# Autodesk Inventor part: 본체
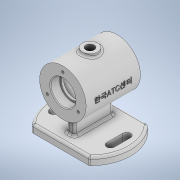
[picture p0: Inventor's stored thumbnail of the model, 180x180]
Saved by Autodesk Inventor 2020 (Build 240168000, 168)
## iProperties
Created: 2021-09
Part Number: 본체
Material: 일반
Document SubType Name: Modeling
Designer: Administrator
Density: 1 g/cm^3
Appearance: 기본값
Author: Administrator
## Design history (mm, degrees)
sketch "스케치1"
  geometry: C1 r 30 at (0, 62); 1 further point
  constraints: 1 centre point, 1 vertical alignment
  dimensions: "d0" = 60 diameter of C1; "d1" = 62 distance of point (0, 0) C1.centre
extrude "돌출1" new body sketch "스케치1" stored distance "d2" = 70; taper "d3" = 0 deg
node "작업 평면1"
sketch "스케치2"
  geometry: L1 (30, 35)-(-30, 35) reference; L2 (30, -35)-(30, 35) reference; C1 r 10 at (0, 0); 1 further point
  constraints: 1 centre point, 1 coincident
  dimensions: "d5" = 35 distance from line of L1 C1.centre; "d65" = 20 diameter of C1
extrude "돌출2" join sketch "스케치2" distance "d6" = 33; taper "d7" = 0 deg
sketch "스케치8"
  geometry: L1 (44.119, 25)-(0, 25); L2 (0, 25)-(0, -25); L3 (0, -25)-(44.119, -25); L4 (44.119, -25)-(44.119, 25); 2 further points
  constraints: 8 end point, 2 parallel, 1 coincident, 1 horizontal, 1 midpoint, 1 perpendicular
  dimensions: "d38" = 50 distance between parallel lines of L3 L1
extrude "돌출6" join sketch "스케치8" stored distance "d39" = 10; taper "d40" = 0 deg
sketch "스케치3"
  geometry: L1 (92, 35)-(32, 35) reference; L2 (32, -35)-(92, -35) reference; L3 (62, 35)-(62, -35); L4 (62, 35)-(78, 35); L5 (78, 35)-(78, 23); L6 (78, 23)-(76, 23); L7 (76, 23)-(76, 20); L8 (76, 20)-(87, 20); L9 (87, 20)-(87, -20); L10 (87, -20)-(76, -20); L11 (76, -20)-(76, -23); L12 (76, -23)-(78, -23); L13 (78, -23)-(78, -35); 1 further point
  constraints: 22 end point, 8 perpendicular, 2 midpoint, 2 point on line, 1 vertical
  dimensions: "d8" = 32 diameter of L5 L3; "d9" = 28 diameter of L7 L3; "d10" = 50 diameter of L9 L3; "d11" = 28 diameter of L11 L3; "d12" = 32 diameter of L13 L3; "d13" = 12 distance from line of L5.end L4; "d14" = 3 distance from line of L8 L5.end; "d15" = 12 distance from line of L2 L11.end; "d16" = 3 distance from line of L11.end L10
revolve "회전1" sketch "스케치3" stored, may be unused: angle "d17" = 90 deg
sketch "스케치4"
  geometry: C1 r 10 at (0, 0) reference; 2 further points
  constraints: 1 coincident
hole "구멍1" sketch "스케치4" at (0, 0) diameter "d18" = 10.917; stored, may be unused: countersink angle "d22" = 90 deg, drill point angle "d24" = 0 deg; dims "d19" = 24, "d20" = 4, "d21" = 2, "d23" = 29.1
sketch "스케치5"
  geometry: C1 r 52.5 at (0, 0); 1 further point
  constraints: 1 centre point, 1 coincident
  dimensions: "d25" = 105 diameter of C1
extrude "돌출3" join sketch "스케치5" distance "d26" = 10; taper "d27" = 0 deg
sketch "스케치6"
  geometry: L1 (-63.077, -37.5)-(63.077, -37.5); L2 (63.077, -37.5)-(63.077, -66.25); L3 (63.077, -66.25)-(-63.077, -66.25); L4 (-63.077, -66.25)-(-63.077, -37.5); L5 (-63.077, 66.25)-(63.077, 66.25); L6 (63.077, 66.25)-(63.077, 37.5); L7 (63.077, 37.5)-(-63.077, 37.5); L8 (-63.077, 37.5)-(-63.077, 66.25); 3 further points
  constraints: 16 end point, 4 parallel, 2 equal length, 2 horizontal, 2 midpoint, 2 perpendicular, 2 vertical alignment
  dimensions: "d28" = 75 distance between parallel lines of L1 L7; "d29" = 37.5 distance from line of point (0, 0) L1
extrude "돌출4" cut sketch "스케치6" extent not by distance; stored distance "d30" = 0; taper "d31" = 0 deg
sketch "스케치7"
  geometry: L1 (-37, 10)-(-37, -10); L2 (-42, 10)-(-42, -10); L3 (-32, -10)-(-32, 10); L4 (37, 10.422)-(37, -10.422); L5 (32, 10.422)-(32, -10.422); L6 (42, -10.422)-(42, 10.422); A1 r 5 centre (-37, 10) between (-32, 10) and (-42, 10); A2 r 5 centre (-37, -10) between (-42, -10) and (-32, -10); A3 r 5 centre (37, 10.422) between (42, 10.422) and (32, 10.422); A4 r 5 centre (37, -10.422) between (32, -10.422) and (42, -10.422); 3 further points
  constraints: 16 end point, 8 point on circle, 8 tangent, 4 centre point, 3 parallel, 2 horizontal alignment, 2 midpoint, 1 equal radius, 1 vertical
  dimensions: "d32" = 20 distance of L1.end L1.start; "d33" = 37 distance of point (0, 0) point (-37, 0); "d34" = 37 distance of point (37, 0) point (0, 0); "d35" = 10 distance between parallel lines of L2 L3
extrude "돌출5" cut sketch "스케치7" extent not by distance; stored distance "d36" = 0; taper "d37" = 0 deg
sketch "스케치9"
  geometry: C1 r 16 at (0, 0) reference; 4 further points
  constraints: 4 other
  dimensions: "d41" = 23 distance of C1.centre point (0, 23); "d44" = 360 deg dimension on C1.centre point (0, 23) (derived)
hole "구멍2" sketch "스케치9" at (0, 23), (-19.919, -11.5), (19.919, -11.5) diameter "d46" = 3.242; stored, may be unused: countersink angle "d50" = 90 deg, drill point angle "d52" = 118 deg; dims "d47" = 8, "d48" = 4, "d49" = 2, "d51" = 10
fillet "모깎기1" dims "d53" = 3
fillet "모깎기2" dims "d54" = 0.3
chamfer "모따기1" distance "d55" = 1; stored, may be unused: second distance "d56" = 2, angle "d57" = 45 deg
fillet "모깎기3" dims "d58" = 3
fillet "모깎기4" dims "d59" = 3
node "작업 평면2"
sketch "스케치10"
  geometry: L1 (92, 35)-(32, 35) reference; L2 (92, -35)-(92, 35) reference; 2 further points
  constraints: 1 other
  dimensions: "d61" = 35 distance from line of point (62, 0) L1; "d62" = 30 distance from line of point (62, 0) L2
feature "엠보싱1" sketch "스케치10" dims "d63" = 0.5, "d64" = 0
node "솔리드1"
mirror "미러1"
feature "A9D066F2-1C7D-4E18-AEED-F7BC21143FA4" dims "d18" = 10.917, "d19" = 24, "d20" = 4, "d21" = 2, "d22" = 90 deg, "d23" = 29.1, "d24" = 0
other parameters: "d4" = 62, "d60" = 70.75
